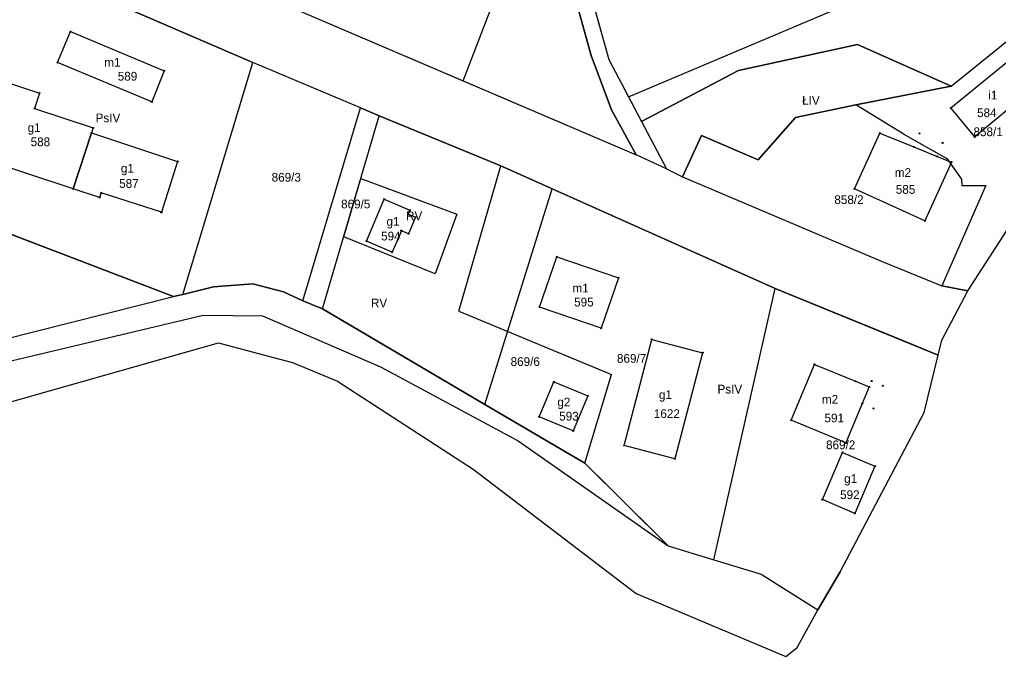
# Model space of a CAD drawing. Extents: x 7498273 to 7499989, y 5499795 to 5500810.
# Drawn here: x 7499733.8 to 7499901.7, y 5499969 to 5500078.2 of the extents above; entities that cross this region are included whole.
import ezdxf

# ---------------------------------------------------------------- set-up
doc = ezdxf.new("R2010")
doc.units = 0
for name, color, linetype in [('209-oznaczenie konturu klasyfikacyjnego', 7, 'Continuous'), ('211-numer działki ewidencyjnej', 7, 'Continuous'), ('217-kontur klasyfikacyjny', 7, 'Continuous'), ('218-kontur użytku gruntowego', 7, 'Continuous'), ('219-działka ewidencyjna', 7, 'Continuous'), ('312-budynek ewidencyjny', 7, 'Continuous'), ('312-oznaczenie budynku ewidencyjnego', 7, 'Continuous'), ('312-oznaczenie budynku ewidencyjnego-Atr117', 7, 'Continuous'), ('Punkt budynku', 7, 'Continuous')]:
    doc.layers.add(name, color=color, linetype=linetype)

# ---------------------------------------------------------------- blocks, each defined once
blk = doc.blocks.new('PUNKTBUD')
blk.add_circle((0, 0), 0.09)

msp = doc.modelspace()

# ---------------------------------------------------------------- linework, layer by layer
at = {"layer": '217-kontur klasyfikacyjny'}
for points in [[(7499809.87, 5500067.68), (7499820.62, 5500095.66)], [(7499773.8, 5500070.79), (7499732.95, 5500088.45)], [(7499831.84, 5500072.04), (7499828.01, 5500085.83)], [(7499769.73, 5500084.85), (7499809.87, 5500067.68)], [(7499832.23, 5500080.7), (7499834.86, 5500071.33)], [(7499838.24, 5500064.92), (7499877.02, 5500081.3)], [(7499877.49, 5500073.91), (7499857.07, 5500069.43)], [(7499893.55, 5500066.75), (7499877.49, 5500073.91)], [(7499835.33, 5500062.68), (7499831.84, 5500072.04)], [(7499765.17, 5500042.2), (7499773.8, 5500070.79)], [(7499792.25, 5500063.04), (7499773.8, 5500070.79)], [(7499834.86, 5500071.33), (7499838.24, 5500064.92)], [(7499857.07, 5500069.43), (7499840.45, 5500060.72)], [(7499809.87, 5500067.68), (7499839.53, 5500055)], [(7499877.21, 5500063.56), (7499893.55, 5500066.75)], [(7499795.49, 5500061.67), (7499792.25, 5500063.04)], [(7499839.53, 5500055), (7499835.33, 5500062.68)], [(7499866.87, 5500061.36), (7499877.21, 5500063.56)], [(7499816.32, 5500053.11), (7499795.49, 5500061.67)], [(7499840.45, 5500060.72), (7499844.74, 5500052.58)], [(7499860.48, 5500054.14), (7499866.87, 5500061.36)], [(7499847.51, 5500051.22), (7499850.73, 5500058.31)], [(7499850.73, 5500058.31), (7499860.48, 5500054.14)], [(7499825.14, 5500049.16), (7499816.32, 5500053.11)], [(7499844.74, 5500052.58), (7499847.51, 5500051.22)], [(7499789.38, 5500040.93), (7499792.33, 5500050.96)], [(7499792.33, 5500050.96), (7499808.76, 5500044.82)], [(7499813.6, 5500012.22), (7499825.14, 5500049.16)], [(7499863.35, 5500032.06), (7499825.14, 5500049.16)], [(7499760.21, 5500030.68), (7499717.86, 5500046.86)], [(7499808.76, 5500044.82), (7499805.06, 5500034.62)], [(7499761.79, 5500031.06), (7499765.17, 5500042.2)], [(7499805.06, 5500034.62), (7499789.38, 5500040.93)], [(7499761.79, 5500031.06), (7499767.03, 5500032.34)], [(7499767.03, 5500032.34), (7499773.8, 5500032.88)], [(7499773.8, 5500032.88), (7499779.05, 5500031.53)], [(7499885.4, 5500023.1), (7499863.35, 5500032.06)], [(7499678.36, 5500010.11), (7499760.21, 5500030.68)], [(7499760.21, 5500030.68), (7499761.79, 5500031.06)], [(7499779.05, 5500031.53), (7499782.36, 5500029.99)], [(7499782.36, 5500029.99), (7499785.74, 5500028.58)], [(7499785.74, 5500028.58), (7499813.6, 5500012.22)], [(7499891.35, 5500020.66), (7499885.4, 5500023.1)], [(7499888.91, 5500010.81), (7499891.35, 5500020.66)], [(7499813.6, 5500012.22), (7499830.73, 5500002.17)], [(7499874.52, 5499983.5), (7499888.91, 5500010.81)], [(7499830.73, 5500002.17), (7499835.1, 5499997.83)], [(7499835.1, 5499997.83), (7499845.03, 5499987.97)], [(7499845.03, 5499987.97), (7499852.85, 5499985.59)], [(7499852.85, 5499985.59), (7499860.97, 5499983.11)], [(7499860.97, 5499983.11), (7499870.69, 5499977)], [(7499870.69, 5499977), (7499874.52, 5499983.5)]]:
    msp.add_lwpolyline(points, dxfattribs=at)
at = {"layer": '218-kontur użytku gruntowego'}
for points in [[(7499809.87, 5500067.68), (7499820.62, 5500095.66)], [(7499773.8, 5500070.79), (7499732.95, 5500088.45)], [(7499831.84, 5500072.04), (7499828.01, 5500085.83)], [(7499769.73, 5500084.85), (7499809.87, 5500067.68)], [(7499832.23, 5500080.7), (7499834.86, 5500071.33)], [(7499838.24, 5500064.92), (7499877.02, 5500081.3)], [(7499857.07, 5500069.43), (7499877.49, 5500073.91)], [(7499877.49, 5500073.91), (7499893.55, 5500066.75)], [(7499835.33, 5500062.68), (7499831.84, 5500072.04)], [(7499765.17, 5500042.2), (7499773.8, 5500070.79)], [(7499792.25, 5500063.04), (7499773.8, 5500070.79)], [(7499834.86, 5500071.33), (7499838.24, 5500064.92)], [(7499840.45, 5500060.72), (7499857.07, 5500069.43)], [(7499809.87, 5500067.68), (7499839.53, 5500055)], [(7499893.55, 5500066.75), (7499877.21, 5500063.56)], [(7499838.24, 5500064.92), (7499840.45, 5500060.72)], [(7499795.49, 5500061.67), (7499792.25, 5500063.04)], [(7499839.53, 5500055), (7499835.33, 5500062.68)], [(7499877.21, 5500063.56), (7499866.87, 5500061.36)], [(7499816.32, 5500053.11), (7499795.49, 5500061.67)], [(7499840.45, 5500060.72), (7499844.74, 5500052.58)], [(7499866.87, 5500061.36), (7499860.48, 5500054.14)], [(7499850.73, 5500058.31), (7499847.51, 5500051.22)], [(7499860.48, 5500054.14), (7499850.73, 5500058.31)], [(7499825.14, 5500049.16), (7499816.32, 5500053.11)], [(7499844.74, 5500052.58), (7499847.51, 5500051.22)], [(7499789.38, 5500040.93), (7499792.33, 5500050.96)], [(7499792.33, 5500050.96), (7499808.76, 5500044.82)], [(7499847.51, 5500051.22), (7499881.7, 5500036.71)], [(7499813.6, 5500012.22), (7499825.14, 5500049.16)], [(7499863.35, 5500032.06), (7499825.14, 5500049.16)], [(7499760.21, 5500030.68), (7499717.86, 5500046.86)], [(7499896.42, 5500031.7), (7499905.5, 5500045.76)], [(7499808.76, 5500044.82), (7499805.06, 5500034.62)], [(7499761.79, 5500031.06), (7499765.17, 5500042.2)], [(7499805.06, 5500034.62), (7499789.38, 5500040.93)], [(7499881.7, 5500036.71), (7499891.94, 5500032.55)], [(7499767.03, 5500032.34), (7499761.79, 5500031.06)], [(7499773.8, 5500032.88), (7499767.03, 5500032.34)], [(7499779.05, 5500031.53), (7499773.8, 5500032.88)], [(7499885.4, 5500023.1), (7499863.35, 5500032.06)], [(7499891.94, 5500032.55), (7499896.42, 5500031.7)], [(7499678.36, 5500010.11), (7499760.21, 5500030.68)], [(7499761.79, 5500031.06), (7499760.21, 5500030.68)], [(7499782.36, 5500029.99), (7499779.05, 5500031.53)], [(7499891.98, 5500023.25), (7499896.42, 5500031.7)], [(7499785.74, 5500028.58), (7499782.36, 5500029.99)], [(7499813.6, 5500012.22), (7499785.74, 5500028.58)], [(7499700.8, 5500012.19), (7499765.3, 5500027.51)], [(7499765.3, 5500027.51), (7499775.44, 5500027.37)], [(7499775.44, 5500027.37), (7499795.7, 5500018.67)], [(7499729.62, 5500011.91), (7499767.93, 5500022.76)], [(7499767.93, 5500022.76), (7499776.26, 5500020.52)], [(7499891.35, 5500020.66), (7499885.4, 5500023.1)], [(7499891.35, 5500020.66), (7499891.98, 5500023.25)], [(7499776.26, 5500020.52), (7499780.58, 5500019.39)], [(7499888.91, 5500010.81), (7499891.35, 5500020.66)], [(7499780.58, 5500019.39), (7499788.33, 5500016.2)], [(7499795.7, 5500018.67), (7499819.29, 5500005.98)], [(7499788.33, 5500016.2), (7499811.6, 5500001.11)], [(7499830.73, 5500002.17), (7499813.6, 5500012.22)], [(7499874.52, 5499983.5), (7499888.91, 5500010.81)], [(7499819.29, 5500005.98), (7499845.03, 5499987.97)], [(7499835.1, 5499997.83), (7499830.73, 5500002.17)], [(7499811.6, 5500001.11), (7499839.52, 5499979.81)], [(7499845.03, 5499987.97), (7499835.1, 5499997.83)], [(7499845.03, 5499987.97), (7499852.85, 5499985.59)], [(7499852.85, 5499985.59), (7499860.97, 5499983.11)], [(7499860.97, 5499983.11), (7499870.69, 5499977)], [(7499870.69, 5499977), (7499874.52, 5499983.5)], [(7499839.52, 5499979.81), (7499865.19, 5499969.02)], [(7499867.14, 5499970.52), (7499870.69, 5499977)], [(7499865.19, 5499969.02), (7499867.14, 5499970.52)]]:
    msp.add_lwpolyline(points, dxfattribs=at)
at = {"layer": '219-działka ewidencyjna'}
for points in [[(7499732.95, 5500088.45), (7499773.8, 5500070.79)], [(7499828.01, 5500085.83), (7499831.84, 5500072.04)], [(7499769.73, 5500084.85), (7499839.53, 5500055)], [(7499831.05, 5500084.88), (7499834.86, 5500071.33)], [(7499893.55, 5500066.75), (7499905.13, 5500076.06)], [(7499831.84, 5500072.04), (7499835.33, 5500062.68)], [(7499765.17, 5500042.2), (7499773.8, 5500070.79)], [(7499792.25, 5500063.04), (7499773.8, 5500070.79)], [(7499834.86, 5500071.33), (7499844.74, 5500052.58)], [(7499877.21, 5500063.56), (7499893.55, 5500066.75)], [(7499675.69, 5500062.97), (7499760.21, 5500030.68)], [(7499782.36, 5500029.99), (7499792.25, 5500063.04)], [(7499792.25, 5500063.04), (7499795.49, 5500061.67)], [(7499835.33, 5500062.68), (7499839.53, 5500055)], [(7499866.87, 5500061.36), (7499877.21, 5500063.56)], [(7499885.3, 5500058.61), (7499877.21, 5500063.56)], [(7499785.74, 5500028.58), (7499795.49, 5500061.67)], [(7499795.49, 5500061.67), (7499816.32, 5500053.11)], [(7499860.48, 5500054.14), (7499866.87, 5500061.36)], [(7499885.3, 5500058.61), (7499892.79, 5500054.34)], [(7499847.51, 5500051.22), (7499850.73, 5500058.31)], [(7499850.73, 5500058.31), (7499860.48, 5500054.14)], [(7499844.74, 5500052.58), (7499839.53, 5500055)], [(7499892.79, 5500054.34), (7499895.35, 5500050.8)], [(7499809.13, 5500028.2), (7499816.32, 5500053.11)], [(7499816.32, 5500053.11), (7499863.35, 5500032.06)], [(7499844.74, 5500052.58), (7499847.51, 5500051.22)], [(7499847.51, 5500051.22), (7499881.7, 5500036.71)], [(7499895.35, 5500050.8), (7499895.41, 5500049.72)], [(7499899.53, 5500049.73), (7499891.94, 5500032.55)], [(7499895.41, 5500049.72), (7499899.53, 5500049.73)], [(7499896.42, 5500031.7), (7499905.5, 5500045.76)], [(7499761.79, 5500031.06), (7499765.17, 5500042.2)], [(7499881.7, 5500036.71), (7499891.94, 5500032.55)], [(7499761.79, 5500031.06), (7499767.03, 5500032.34)], [(7499767.03, 5500032.34), (7499773.8, 5500032.88)], [(7499773.8, 5500032.88), (7499779.05, 5500031.53)], [(7499852.85, 5499985.59), (7499863.35, 5500032.06)], [(7499863.35, 5500032.06), (7499891.35, 5500020.66)], [(7499896.42, 5500031.7), (7499891.94, 5500032.55)], [(7499678.36, 5500010.11), (7499760.21, 5500030.68)], [(7499760.21, 5500030.68), (7499761.79, 5500031.06)], [(7499782.36, 5500029.99), (7499779.05, 5500031.53)], [(7499891.98, 5500023.25), (7499896.42, 5500031.7)], [(7499782.36, 5500029.99), (7499785.74, 5500028.58)], [(7499785.74, 5500028.58), (7499830.73, 5500002.17)], [(7499809.13, 5500028.2), (7499835.31, 5500017.34)], [(7499729.62, 5500011.91), (7499767.93, 5500022.76)], [(7499767.93, 5500022.76), (7499776.26, 5500020.52)], [(7499891.35, 5500020.66), (7499891.98, 5500023.25)], [(7499776.26, 5500020.52), (7499780.58, 5500019.39)], [(7499888.91, 5500010.81), (7499891.35, 5500020.66)], [(7499780.58, 5500019.39), (7499788.33, 5500016.2)], [(7499830.73, 5500002.17), (7499835.31, 5500017.34)], [(7499788.33, 5500016.2), (7499811.6, 5500001.11)], [(7499874.52, 5499983.5), (7499888.91, 5500010.81)], [(7499830.73, 5500002.17), (7499845.03, 5499987.97)], [(7499811.6, 5500001.11), (7499839.52, 5499979.81)], [(7499845.03, 5499987.97), (7499852.85, 5499985.59)], [(7499852.85, 5499985.59), (7499860.97, 5499983.11)], [(7499860.97, 5499983.11), (7499870.69, 5499977)], [(7499874.52, 5499983.5), (7499870.69, 5499977)], [(7499839.52, 5499979.81), (7499865.19, 5499969.02)], [(7499867.14, 5499970.52), (7499870.69, 5499977)], [(7499865.19, 5499969.02), (7499867.14, 5499970.52)]]:
    msp.add_lwpolyline(points, dxfattribs=at)
at = {"layer": '312-budynek ewidencyjny'}
for points in [[(7499740.3, 5500070.81), (7499742.52, 5500076.12)], [(7499742.52, 5500076.12), (7499758.58, 5500069.41)], [(7499756.47, 5500064.05), (7499740.3, 5500070.81)], [(7499893.51, 5500063.02), (7499903.08, 5500070.89)], [(7499758.58, 5500069.41), (7499756.47, 5500064.05)], [(7499732.05, 5500067.29), (7499737.21, 5500065.58)], [(7499737.21, 5500065.58), (7499736.34, 5500062.94)], [(7499907.16, 5500065.94), (7499897.59, 5500058.07)], [(7499736.34, 5500062.94), (7499746.43, 5500059.59)], [(7499897.59, 5500058.07), (7499893.51, 5500063.02)], [(7499746.14, 5500058.74), (7499742.97, 5500049.16)], [(7499742.97, 5500049.16), (7499746.14, 5500058.74)], [(7499746.43, 5500059.59), (7499746.14, 5500058.74)], [(7499746.14, 5500058.74), (7499760.9, 5500053.85)], [(7499876.98, 5500049.16), (7499881.33, 5500058.72)], [(7499881.33, 5500058.72), (7499887.17, 5500056.35)], [(7499887.17, 5500056.35), (7499891.15, 5500054.73)], [(7499742.97, 5500049.16), (7499726.88, 5500054.5)], [(7499760.9, 5500053.85), (7499758.11, 5500045.14)], [(7499893.61, 5500053.73), (7499889.03, 5500043.67)], [(7499891.15, 5500054.73), (7499893.61, 5500053.73)], [(7499747.52, 5500047.7), (7499742.97, 5500049.16)], [(7499889.03, 5500043.67), (7499876.98, 5500049.16)], [(7499747.77, 5500048.48), (7499747.52, 5500047.7)], [(7499758.11, 5500045.14), (7499747.77, 5500048.48)], [(7499793.27, 5500040.18), (7499796.32, 5500047.37)], [(7499796.32, 5500047.37), (7499800.72, 5500045.52)], [(7499800.72, 5500045.52), (7499800.44, 5500044.82)], [(7499800.44, 5500044.82), (7499801.7, 5500044.3)], [(7499801.7, 5500044.3), (7499800.51, 5500041.46)], [(7499799.27, 5500041.99), (7499797.69, 5500038.29)], [(7499800.51, 5500041.46), (7499799.27, 5500041.99)], [(7499797.69, 5500038.29), (7499793.27, 5500040.18)], [(7499822.98, 5500028.89), (7499825.93, 5500037.52)], [(7499825.93, 5500037.52), (7499836.49, 5500033.91)], [(7499836.49, 5500033.91), (7499833.54, 5500025.28)], [(7499833.54, 5500025.28), (7499822.98, 5500028.89)], [(7499837.47, 5500005.18), (7499842.23, 5500023.36)], [(7499842.23, 5500023.36), (7499850.94, 5500021.08)], [(7499850.94, 5500021.08), (7499846.18, 5500002.9)], [(7499866.11, 5500009.5), (7499870.14, 5500019.08)], [(7499870.14, 5500019.08), (7499877.14, 5500016.18)], [(7499822.92, 5500010.07), (7499825.41, 5500016.08)], [(7499825.41, 5500016.08), (7499831.23, 5500013.67)], [(7499877.14, 5500016.18), (7499879.5, 5500015.2)], [(7499879.5, 5500015.2), (7499878.31, 5500012.34)], [(7499831.23, 5500013.67), (7499828.74, 5500007.66)], [(7499878.31, 5500012.34), (7499875.51, 5500005.6)], [(7499828.74, 5500007.66), (7499822.92, 5500010.07)], [(7499875.51, 5500005.6), (7499866.11, 5500009.5)], [(7499846.18, 5500002.9), (7499837.47, 5500005.18)], [(7499871.47, 5499995.9), (7499874.93, 5500003.99)], [(7499874.93, 5500003.99), (7499880.49, 5500001.61)], [(7499880.49, 5500001.61), (7499877.03, 5499993.52)], [(7499877.03, 5499993.52), (7499871.47, 5499995.9)]]:
    msp.add_lwpolyline(points, dxfattribs=at)

# ---------------------------------------------------------------- block references
at = {"layer": 'Punkt budynku'}
for p in [(7499742.52, 5500076.12), (7499740.3, 5500070.81), (7499758.58, 5500069.41), (7499737.21, 5500065.58), (7499756.47, 5500064.05), (7499736.34, 5500062.94), (7499893.51, 5500063.02), (7499746.14, 5500058.74), (7499746.43, 5500059.59), (7499881.33, 5500058.72), (7499888.11, 5500058.66), (7499892.1, 5500057.04), (7499897.59, 5500058.07), (7499887.17, 5500056.35), (7499760.9, 5500053.85), (7499891.15, 5500054.73), (7499893.61, 5500053.73), (7499742.97, 5500049.16), (7499747.77, 5500048.48), (7499876.98, 5500049.16), (7499747.52, 5500047.7), (7499796.32, 5500047.37), (7499758.11, 5500045.14), (7499800.72, 5500045.52), (7499800.44, 5500044.82), (7499801.7, 5500044.3), (7499889.03, 5500043.67), (7499799.27, 5500041.99), (7499793.27, 5500040.18), (7499800.51, 5500041.46), (7499797.69, 5500038.29), (7499825.93, 5500037.52), (7499836.49, 5500033.91), (7499822.98, 5500028.89), (7499833.54, 5500025.28), (7499842.23, 5500023.36), (7499850.94, 5500021.08), (7499870.14, 5500019.08), (7499825.41, 5500016.08), (7499877.14, 5500016.18), (7499879.5, 5500015.2), (7499879.92, 5500016.21), (7499881.86, 5500015.41), (7499831.23, 5500013.67), (7499878.31, 5500012.34), (7499880.25, 5500011.53), (7499822.92, 5500010.07), (7499866.11, 5500009.5), (7499828.74, 5500007.66), (7499837.47, 5500005.18), (7499875.51, 5500005.6), (7499874.93, 5500003.99), (7499846.18, 5500002.9), (7499880.49, 5500001.61), (7499871.47, 5499995.9), (7499877.03, 5499993.52)]:
    msp.add_blockref('PUNKTBUD', p, dxfattribs=at)

# ---------------------------------------------------------------- texts
at = {"layer": '209-oznaczenie konturu klasyfikacyjnego'}
for s, p in [('ŁIV', (7499868, 5500063.57)), ('PsIV', (7499746.83, 5500060.57)), ('RV', (7499800.07, 5500043.79)), ('RV', (7499794.05, 5500028.85)), ('PsIV', (7499853.48, 5500014.08))]:
    msp.add_text(s, height=1.5, dxfattribs=at).set_placement(p)
at = {"layer": '211-numer działki ewidencyjnej'}
for s, p in [('858/1', (7499897.39, 5500058.19)), ('869/3', (7499777.02, 5500050.39)), ('869/5', (7499788.93, 5500045.81)), ('858/2', (7499873.52, 5500046.56)), ('869/6', (7499818, 5500018.8)), ('869/7', (7499836.24, 5500019.35)), ('869/2', (7499872.1, 5500004.53))]:
    msp.add_text(s, height=1.5, dxfattribs=at).set_placement(p)
at = {"layer": '312-oznaczenie budynku ewidencyjnego'}
for s, p in [('589', (7499750.63, 5500067.71)), ('584', (7499898, 5500061.45)), ('588', (7499735.69, 5500056.47)), ('587', (7499750.87, 5500049.33)), ('585', (7499884.06, 5500048.31)), ('594', (7499795.79, 5500040.32)), ('595', (7499828.9, 5500029)), ('593', (7499826.34, 5500009.45)), ('1622', (7499842.57, 5500009.88)), ('591', (7499871.84, 5500009.13)), ('592', (7499874.51, 5499995.99))]:
    msp.add_text(s, height=1.5, dxfattribs=at).set_placement(p)
at = {"layer": '312-oznaczenie budynku ewidencyjnego-Atr117'}
for s, p in [('m1', (7499748.315, 5500070.09)), ('i1', (7499899.922, 5500064.48)), ('g1', (7499735.18, 5500058.9)), ('g1', (7499751.169, 5500051.94)), ('m2', (7499883.886, 5500051.2)), ('g1', (7499796.719, 5500042.83)), ('m1', (7499828.615, 5500031.4)), ('g2', (7499826.019, 5500011.87)), ('g1', (7499843.439, 5500013.13)), ('m2', (7499871.396, 5500012.34)), ('g1', (7499875.209, 5499998.76))]:
    msp.add_text(s, height=1.5, dxfattribs=at).set_placement(p)

doc.saveas('drawing.dxf')
